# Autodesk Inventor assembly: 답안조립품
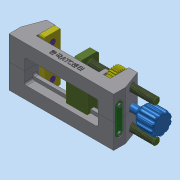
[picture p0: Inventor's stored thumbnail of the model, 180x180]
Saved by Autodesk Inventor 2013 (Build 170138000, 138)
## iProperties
Created: 2017-04
Part Number: 답안조립품
Document SubType Name: Assembly
Designer: dgall
Author: dgall
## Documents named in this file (10)
- C:\Users\dgall\Desktop\370407V1005\답안조립품.iam
- C:\Users\dgall\Desktop\370407V1005\바이스본체 A.ipt
- C:\Users\dgall\Desktop\370407V1005\바이스본체 B.ipt
- C:\Users\dgall\Desktop\370407V1005\지지대.ipt
- C:\Users\dgall\Desktop\370407V1005\십자오목머리나사 M4.ipt
- C:\Users\dgall\Desktop\370407V1005\고정 플레이트.ipt
- C:\Users\dgall\Desktop\370407V1005\십자오목머리나사 M3.ipt
- C:\Users\dgall\Desktop\370407V1005\슬라이딩 부품.ipt
- C:\Users\dgall\Desktop\370407V1005\핸들.ipt
- C:\Users\dgall\Desktop\370407V1005\스퍼기어.ipt
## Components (3 placed, 2 different names)
1. 고정 플레이트:1
2. 핸들:1
3. 고정 플레이트:2
